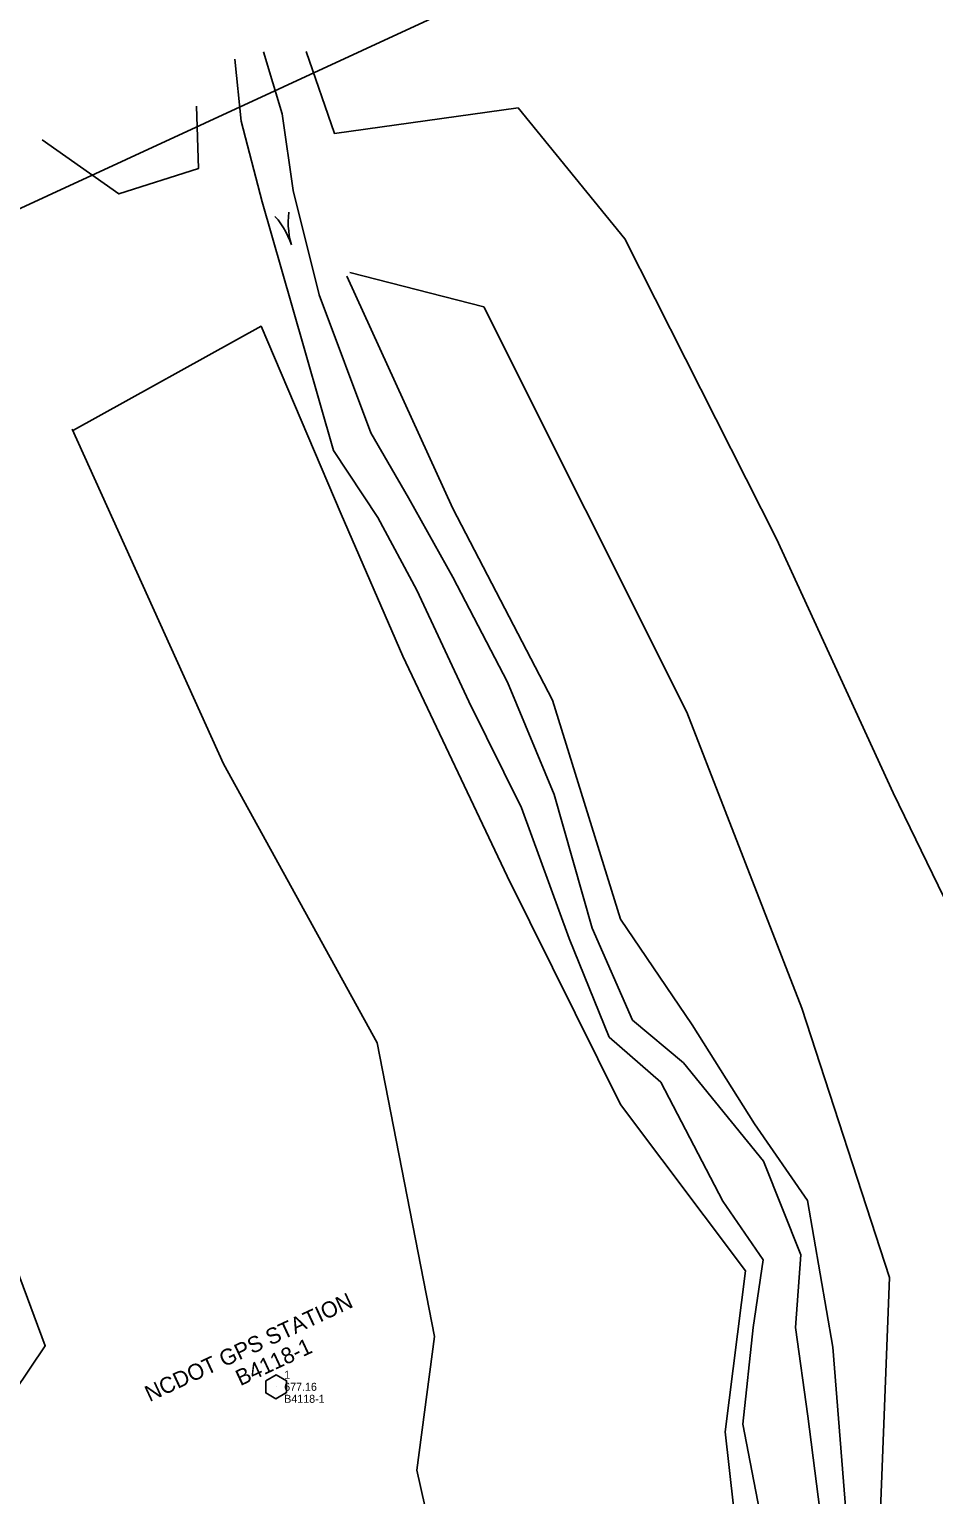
# Model space of a CAD drawing. Extents: x 1380524 to 1382335, y 594765 to 596944.
# Drawn here: x 1381250.1 to 1381532.7, y 596218 to 596675.7 of the extents above; entities that cross this region are included whole.
import ezdxf

# ---------------------------------------------------------------- set-up
doc = ezdxf.new("R2010")
doc.units = 0
for name, color, linetype in [('CTL GPS Vertical CELL', 7, 'Continuous'), ('CTL GPS Vertical Cogo Comment', 7, 'Continuous'), ('CTL GPS Vertical Cogo Elevation', 7, 'Continuous'), ('CTL GPS Vertical Cogo Number', 7, 'Continuous'), ('CTL GPS Vertical Text', 7, 'Continuous'), ('DTM Contours Minor Text', 7, 'Continuous'), ('Exist Hydro Jurisdictional Stream or Body of Water', 7, 'Continuous'), ('Prop Drainage Structure Box Number Symbol CELL', 7, 'Continuous'), ('Prop Earthen Structure Cut Ditch Special Detail Label', 7, 'Continuous'), ('Prop Plan Preparation Design Box Number Symbol CELL', 7, 'Continuous')]:
    doc.layers.add(name, color=color, linetype=linetype)

# ---------------------------------------------------------------- blocks, each defined once
blk = doc.blocks.new('EXIST HYDRO STREAM FLOW ARROW')
at = {"layer": 'DTM Contours Minor Text'}
blk.add_line((0, 0), (0, 0), dxfattribs=at)
for points in [[(-0.1, 0.04575), (-0.07325, 0.03375), (-0.04475, 0.0245), (-0.0165, 0.01575), (0.01175, 0.0095), (0.041, 0.00475), (0.07075, 0.0015), (0.1, 0)], [(-0.1, -0.04575), (-0.07325, -0.03375), (-0.04475, -0.0245), (-0.0165, -0.01575), (0.01175, -0.0095), (0.041, -0.00475), (0.07075, -0.0015), (0.1, 0)]]:
    blk.add_lwpolyline(points, dxfattribs=at)

msp = doc.modelspace()

# ---------------------------------------------------------------- linework, layer by layer
at = {"layer": 'CTL GPS Vertical CELL'}
msp.add_line((1381327.21, 596251.68), (1381327.21, 596251.68), dxfattribs=at)
msp.add_lwpolyline([(1381323.98, 596253.55), (1381327.23, 596255.36), (1381330.48, 596253.57), (1381330.43, 596249.85), (1381327.18, 596247.96), (1381323.98, 596249.77)], close=True, dxfattribs=at)
at = {"layer": 'Exist Hydro Jurisdictional Stream or Body of Water'}
for points in [[(1381483.77, 596135.72), (1381491.96, 596152.52), (1381503.81, 596172.33), (1381498.26, 596204.27), (1381493.33, 596242.46), (1381489.5, 596270.15), (1381491.18, 596292.87), (1381479.48, 596322.14), (1381454.47, 596352.84), (1381438.58, 596366.23), (1381425.98, 596394.97), (1381414.1, 596436.71), (1381399.5, 596471.74), (1381382.49, 596504.52), (1381368.62, 596529.32), (1381356.86, 596549.69), (1381340.72, 596592.72), (1381332.5, 596625.31), (1381329.08, 596649.3), (1381323.28, 596668.67)], [(1381470.05, 596141.17), (1381479.15, 596157.42), (1381487.89, 596174.59), (1381480.55, 596201.17), (1381473.06, 596240.03), (1381476.26, 596270.23), (1381479.45, 596291.3), (1381466.84, 596309.68), (1381447.4, 596346.85), (1381431.33, 596360.89), (1381418.79, 596391.67), (1381403.92, 596432.5), (1381387.45, 596465.68), (1381371.16, 596500.46), (1381359.03, 596523.24), (1381345.11, 596544.14), (1381332.16, 596589.54), (1381322.88, 596621.8), (1381316.31, 596646.98), (1381314.3, 596666.4)]]:
    msp.add_lwpolyline(points, dxfattribs=at)
at = {"layer": 'Prop Drainage Structure Box Number Symbol CELL'}
msp.add_lwpolyline([(1382083.99, 595964.39), (1380966.64, 596251.47), (1381106.82, 596554.99), (1381897.61, 596920.15), (1382148.43, 596473.2)], close=True, dxfattribs=at)
at = {"layer": 'Prop Earthen Structure Cut Ditch Special Detail Label'}
for points in [[(1381993.97, 596746.39), (1381926.82, 596678.09), (1381882.73, 596673.31), (1381857.71, 596563.06), (1381849.31, 596464.5), (1381837.19, 596379.89), (1381830.78, 596342.77), (1381810.83, 596299.24), (1381745.1, 596224.39), (1381733.09, 596194.6), (1381689.78, 596209.04), (1381619.47, 596192.74), (1381567.86, 596179.57), (1381583.81, 596285.11), (1381565.74, 596343.12), (1381520.02, 596437.2), (1381483.63, 596516.56), (1381436.21, 596610.27), (1381402.81, 596651.16), (1381345.44, 596643.18), (1381336.65, 596668.79)], [(1381302.32, 596651.72), (1381303.02, 596632.25), (1381278.08, 596624.25), (1381254.08, 596641.21)], [(1381350.25, 596599.71), (1381392.08, 596589.01), (1381455.55, 596462.39), (1381491.49, 596369.91), (1381518.9, 596285.84), (1381513.37, 596143.29), (1381495.81, 596147.64), (1381508.01, 596177.5), (1381501.15, 596264.04), (1381493.24, 596309.84), (1381476.75, 596333.82), (1381457.25, 596364.74), (1381434.82, 596397.71), (1381413.54, 596466.18), (1381382.47, 596526.06), (1381349.37, 596598.57)], [(1381263.88, 596550.5), (1381322.53, 596582.96), (1381347.53, 596524.27), (1381366.83, 596479.87), (1381399.39, 596411.16), (1381434.84, 596339.9), (1381473.87, 596287.88), (1381467.51, 596237.62), (1381474.2, 596178.18), (1381465.81, 596148.7)], [(1381387.07, 596155), (1381371.17, 596225.61), (1381376.7, 596267.4), (1381358.82, 596359.09), (1381310.74, 596446.26), (1381263.45, 596550.77)], [(1381099.67, 596544.32), (1381188.54, 596443.63), (1381255.07, 596264.49), (1381230.85, 596228.68), (1381172.77, 596290.45), (1381161.09, 596312.72), (1381151.97, 596361.33), (1381152.87, 596409.75), (1381100, 596443.47), (1381063.73, 596438.1), (1381070.19, 596392.54), (1381064.84, 596337.41), (1381117.05, 596324.33), (1381112.45, 596306.47), (1380991.53, 596311.89)]]:
    msp.add_lwpolyline(points, dxfattribs=at)

# ---------------------------------------------------------------- block references
at = {"layer": 'Prop Plan Preparation Design Box Number Symbol CELL', "xscale": 50, "yscale": 50, "rotation": -72.95173055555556}
msp.add_blockref('EXIST HYDRO STREAM FLOW ARROW', (1381330.52, 596613.14), dxfattribs=at)

# ---------------------------------------------------------------- texts
at = {"layer": 'CTL GPS Vertical Cogo Comment'}
msp.add_text('B4118-1', height=2.5, dxfattribs=at).set_placement((1381329.74, 596246.67))
at = {"layer": 'CTL GPS Vertical Cogo Elevation'}
msp.add_text('677.16', height=2.5, dxfattribs=at).set_placement((1381329.74, 596250.42))
at = {"layer": 'CTL GPS Vertical Cogo Number'}
msp.add_text('1', height=2.5, dxfattribs=at).set_placement((1381329.74, 596254.17))
at = {"layer": 'CTL GPS Vertical Text'}
for s, p in [('NCDOT GPS STATION', (1381287.69, 596246.9)), ('B4118-1', (1381316.05, 596251.85))]:
    msp.add_text(s, height=5, rotation=25, dxfattribs=at).set_placement(p)

doc.saveas('drawing.dxf')
